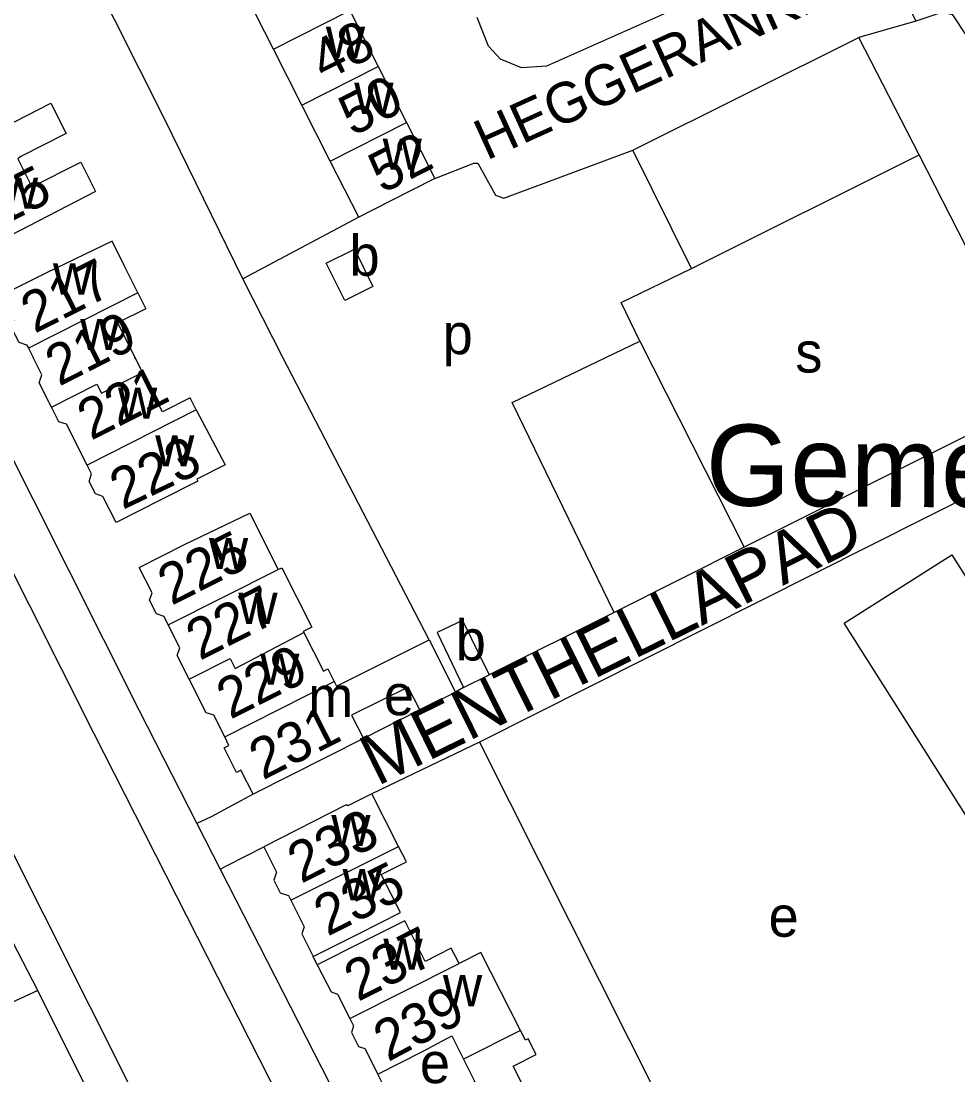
# Model space of a CAD drawing. Extents: x 161258 to 163262, y 380749 to 382054.
# Drawn here: x 162448.7 to 162541.1, y 381429.2 to 381533.2 of the extents above; entities that cross this region are included whole.
import ezdxf

# ---------------------------------------------------------------- set-up
doc = ezdxf.new("R2010")
doc.units = 0
for name, color, linetype in [('BLT_Basislijn', 7, 'Continuous'), ('BLT_Bebouwing', 7, 'Continuous'), ('BLT_Bebouwing_beschrifting', 7, 'Continuous'), ('BLT_Centroide', 7, 'Continuous'), ('BLT_Huisnummer', 7, 'Continuous'), ('BLT_Huisnummer_ tussenligend', 7, 'Continuous'), ('BLT_Onderverdeling_panden', 7, 'Continuous'), ('BLT_Straatnaam', 7, 'Continuous'), ('BLT_Straatnaam_verkleind', 7, 'Continuous')]:
    doc.layers.add(name, color=color, linetype=linetype)

msp = doc.modelspace()

# ---------------------------------------------------------------- linework, layer by layer
at = {"layer": 'BLT_Basislijn'}
for p, q in [((162416.03, 381553.18), (162460.34, 381465.23)), ((162411.57, 381550.93), (162455.87, 381462.98)), ((162536.9, 381533.15), (162531.28, 381531.53)), ((162537.23, 381519.98), (162531.28, 381531.53)), ((162514.8, 381508.76), (162509, 381520.42)), ((162514.8, 381508.76), (162537.23, 381519.98)), ((162547.55, 381499.74), (162537.23, 381519.98)), ((162482, 381513.83), (162470.57, 381507.75)), ((162507.86, 381505.42), (162514.8, 381508.76)), ((162509.71, 381501.59), (162507.86, 381505.42)), ((162497.11, 381495.54), (162509.71, 381501.59)), ((162509.71, 381501.59), (162520, 381481.27)), ((162560.67, 381495.67), (162493.89, 381462.07)), ((162549.4, 381496.02), (162520, 381481.27)), ((162507.17, 381474.84), (162497.11, 381495.54)), ((162520, 381481.27), (162507.17, 381474.84)), ((162435.76, 381475.3), (162471.25, 381404.61)), ((162507.17, 381474.84), (162494.86, 381468.68)), ((162492.34, 381467.44), (162491.54, 381466.98)), ((162460.34, 381465.23), (162466.05, 381454.03)), ((162488.02, 381465.23), (162482.46, 381462.42)), ((162455.87, 381462.98), (162475.39, 381424.52)), ((162493.89, 381462.07), (162483.3, 381456.97)), ((162493.89, 381462.07), (162518.15, 381413.86)), ((162471.59, 381456.91), (162467.46, 381454.7)), ((162467.46, 381454.7), (162466.05, 381454.03)), ((162466.05, 381454.03), (162468.35, 381449.53)), ((162469.05, 381449.89), (162472.64, 381451.74)), ((162468.35, 381449.53), (162469.05, 381449.89)), ((162468.35, 381449.53), (162480.15, 381426.41)), ((162477.92, 381440.11), (162477.51, 381440.92)), ((162450.39, 381437.58), (162444.45, 381434.82)), ((162460.82, 381416.55), (162450.39, 381437.58)), ((162486.13, 381424.89), (162483.88, 381429.32))]:
    msp.add_line(p, q, dxfattribs=at)
for points in [[(162450.39, 381437.58), (162418.09, 381500), (162384.62, 381565.32)], [(162470.57, 381507.75), (162462.89, 381523.46), (162443.04, 381562.88)], [(162532.07, 381550.22), (162534.53, 381545.25), (162534.67, 381544.33), (162533.91, 381543.61), (162500.52, 381528.7), (162498.03, 381528.54), (162495.96, 381529.41), (162494.78, 381530.68), (162493.68, 381533.5)], [(162631.05, 381395.39), (162633.35, 381398.89), (162632.9, 381403.53), (162624.97, 381412.12), (162615.66, 381424.45), (162600, 381449.93), (162569.46, 381500), (162544.3, 381537.15), (162543.02, 381538.49), (162542.38, 381538.78), (162539.8, 381539.21), (162535.12, 381537.37), (162535.12, 381536.9), (162536.9, 381533.15)], [(162549.4, 381496.02), (162556.96, 381500), (162560.62, 381501.86), (162560.84, 381502.53), (162549.84, 381519.11), (162545.67, 381526.01), (162540.54, 381533.77), (162539.48, 381534.01), (162536.9, 381533.15)], [(162509, 381520.42), (162531.28, 381531.53)], [(162489.51, 381517.63), (162493.36, 381519.16), (162493.74, 381519.16), (162495.47, 381515.98), (162496.29, 381515.7), (162509, 381520.42)], [(162488.94, 381472.14), (162474.51, 381500), (162470.57, 381507.75)]]:
    msp.add_lwpolyline(points, dxfattribs=at)
at = {"layer": 'BLT_Bebouwing'}
for p, q in [((162473.61, 381530.38), (162470.82, 381535.9)), ((162481.13, 381534.19), (162483.92, 381528.67)), ((162476.41, 381524.87), (162473.61, 381530.38)), ((162483.92, 381528.67), (162486.71, 381523.15)), ((162479.2, 381519.35), (162476.41, 381524.87)), ((162486.71, 381523.15), (162489.51, 381517.63)), ((162482, 381513.83), (162479.2, 381519.35)), ((162449.44, 381500.91), (162449.9, 381500)), ((162460, 381499.88), (162459.94, 381500)), ((162492.24, 381474.06), (162494.86, 381468.68)), ((162492.34, 381467.44), (162494.86, 381468.68)), ((162488.02, 381465.23), (162491.54, 381466.98)), ((162482.46, 381462.42), (162471.59, 381456.91)), ((162552.63, 381437.72), (162537.06, 381462.39)), ((162485.93, 381451.77), (162483.3, 381456.97))]:
    msp.add_line(p, q, dxfattribs=at)
for points in [[(162445.35, 381525.55), (162446.85, 381522.6), (162451.66, 381525.05), (162453.17, 381522.08), (162448.7, 381519.81), (162448.39, 381519.59)], [(162448.39, 381519.59), (162449.8, 381516.82), (162454.6, 381519.26), (162456.07, 381516.37), (162447.61, 381511.99), (162443.15, 381509.72), (162441.61, 381512.75), (162440.95, 381512.97), (162440.25, 381514.34), (162440.48, 381515.05), (162440.27, 381515.45)], [(162489.51, 381517.63), (162485.05, 381515.37), (162482, 381513.83)], [(162460.23, 381506.37), (162458.9, 381509.07), (162457.71, 381511.45), (162451.22, 381508.35), (162446.76, 381506.09), (162447.99, 381503.64), (162447.76, 381502.93), (162448.49, 381501.49), (162449.27, 381501.24), (162449.44, 381500.91)], [(162460.23, 381506.37), (162461.02, 381504.8), (162458.22, 381503.39), (162460.68, 381498.52)], [(162451.71, 381495.1), (162450.5, 381497.49), (162450.76, 381498.29), (162449.9, 381500)], [(162465.99, 381494.82), (162465.39, 381496.01), (162462.66, 381494.63), (162460.68, 381498.52)], [(162455.24, 381489.38), (162453.21, 381493.4), (162452.44, 381493.65), (162451.71, 381495.1)], [(162465.99, 381494.82), (162468.85, 381489.4), (162466.04, 381487.98), (162466.14, 381487.78), (162462.55, 381485.97), (162458.09, 381483.71)], [(162458.09, 381483.71), (162456.79, 381486.28), (162456.05, 381486.53), (162455.43, 381487.75), (162455.68, 381488.52), (162455.24, 381489.38)], [(162460.35, 381479.29), (162464.82, 381481.55), (162471.26, 381484.63), (162474.07, 381479.08)], [(162537.06, 381462.39), (162529.85, 381473.8), (162540.47, 381480.51), (162552.78, 381461)], [(162463.23, 381473.64), (162462.81, 381474.46), (162462.06, 381474.71), (162461.39, 381476.04), (162461.63, 381476.77), (162460.35, 381479.29)], [(162474.07, 381479.08), (162474.42, 381479.26), (162477.39, 381473.39)], [(162492.24, 381474.06), (162489.74, 381472.86), (162492.34, 381467.44)], [(162465.29, 381468.27), (162464.12, 381470.59), (162464.38, 381471.37), (162463.23, 381473.64)], [(162477.39, 381473.39), (162476.54, 381472.96), (162476.59, 381472.86)], [(162476.59, 381472.86), (162478.52, 381469.06), (162478.95, 381469.28), (162479.59, 381468.02)], [(162479.59, 381468.02), (162479.82, 381467.56), (162488.94, 381472.14)], [(162488.94, 381472.14), (162491.54, 381466.98)], [(162468.79, 381462.59), (162467.71, 381464.71), (162466.97, 381464.95), (162465.29, 381468.27)], [(162488.02, 381465.23), (162486.89, 381467.48), (162481.29, 381464.73), (162482.46, 381462.42)], [(162471.59, 381456.91), (162470.39, 381459.28), (162469.96, 381459.07), (162468.73, 381461.5), (162469.21, 381461.74), (162468.79, 381462.59)], [(162483.3, 381456.97), (162480.92, 381455.76), (162480.77, 381455.86), (162472.64, 381451.74)], [(162472.64, 381451.74), (162473.9, 381449.25), (162473.64, 381448.44), (162474.27, 381447.2), (162475.07, 381446.93), (162475.31, 381446.47)], [(162477.51, 381440.92), (162481.97, 381443.17), (162486.12, 381445.26), (162484.22, 381449), (162486.7, 381450.26), (162485.93, 381451.77)], [(162475.31, 381446.47), (162476.62, 381443.86), (162476.39, 381443.14), (162477.51, 381440.92)], [(162491.89, 381440.22), (162491.12, 381441.73), (162488.56, 381440.43), (162486.54, 381444.44), (162482.39, 381442.35), (162477.92, 381440.11)], [(162497.96, 381433.61), (162494.02, 381441.31), (162491.89, 381440.22)], [(162477.92, 381440.11), (162479.28, 381437.43), (162479.9, 381437.22), (162481.12, 381434.82)], [(162481.12, 381434.82), (162481.49, 381434.08), (162481.28, 381433.43), (162481.98, 381432.05), (162482.6, 381431.84), (162483.88, 381429.32)], [(162496.96, 381423.89), (162495.65, 381426.46), (162498.36, 381427.83), (162497.21, 381430.1), (162499.48, 381431.27), (162498.69, 381432.81), (162498.44, 381432.68), (162497.96, 381433.61)], [(162483.88, 381429.32), (162488.34, 381431.58), (162491.17, 381433.08), (162492.32, 381430.8)], [(162492.32, 381430.8), (162493.46, 381428.55), (162486.13, 381424.89)]]:
    msp.add_lwpolyline(points, dxfattribs=at)
msp.add_lwpolyline([(162478.8, 381509.3), (162481.57, 381510.67), (162483.39, 381507), (162480.62, 381505.62)], close=True, dxfattribs=at)
at = {"layer": 'BLT_Onderverdeling_panden'}
for p, q in [((162473.61, 381530.38), (162481.13, 381534.19)), ((162476.41, 381524.87), (162483.92, 381528.67)), ((162479.2, 381519.35), (162486.71, 381523.15)), ((162460.23, 381506.37), (162449.44, 381500.91)), ((162465.99, 381494.82), (162455.24, 381489.38)), ((162463.23, 381473.64), (162474.07, 381479.08)), ((162468.79, 381462.59), (162479.59, 381468.02)), ((162475.31, 381446.47), (162485.93, 381451.77)), ((162481.12, 381434.82), (162491.89, 381440.22)), ((162497.96, 381433.61), (162492.32, 381430.8))]:
    msp.add_line(p, q, dxfattribs=at)
for points in [[(162451.71, 381495.1), (162456.2, 381497.37), (162456.65, 381496.48), (162460.68, 381498.52)], [(162465.29, 381468.27), (162469.34, 381470.3), (162469.83, 381469.32), (162476.59, 381472.86)]]:
    msp.add_lwpolyline(points, dxfattribs=at)

# ---------------------------------------------------------------- texts
at = {"layer": 'BLT_Bebouwing_beschrifting'}
msp.add_text('Gemeenschapshuis', height=7.9999, rotation=359.548, dxfattribs=at).set_placement((162516.18, 381485.4))
at = {"layer": 'BLT_Centroide'}
for s, p in [('w', (162478.77, 381529.53)), ('w', (162481.56, 381524)), ('w', (162484.36, 381518.5)), ('w', (162446.55, 381514.66)), ('b', (162481.09, 381508.04)), ('w', (162451.87, 381506.19)), ('w', (162454.55, 381500.72)), ('p', (162490.27, 381500.31)), ('s', (162525.03, 381498.5)), ('w', (162458.28, 381493.94)), ('w', (162461.94, 381489.25)), ('w', (162467.24, 381479.12)), ('w', (162470.14, 381473.72)), ('b', (162491.56, 381470.11)), ('w', (162472.29, 381467.72)), ('m', (162477.02, 381464.53)), ('e', (162484.48, 381464.71)), ('w', (162479.3, 381451.81)), ('w', (162480.41, 381446.47)), ('e', (162522.39, 381442.87)), ('w', (162484.43, 381439.62)), ('w', (162490.3, 381436.02)), ('e', (162488.03, 381428.43))]:
    msp.add_text(s, height=4, dxfattribs=at).set_placement(p)
at = {"layer": 'BLT_Huisnummer'}
for s, rotation, p in [('52', 26.8367, (162484.32, 381516.11)), ('215', 26.9698, (162444.06, 381511.49)), ('217', 26.8466, (162450.06, 381502.31)), ('223', 25.5496, (162458.74, 381484.94)), ('225', 26.859, (162463.55, 381475.48)), ('231', 26.8547, (162472.55, 381458.27)), ('233', 26.7547, (162476.33, 381448.07)), ('239', 27.9921, (162484.88, 381430.49))]:
    msp.add_text(s, height=4, rotation=rotation, dxfattribs=at).set_placement(p)
at = {"layer": 'BLT_Huisnummer_ tussenligend'}
for s, rotation, p in [('48', 26.8544, (162478.59, 381527.17)), ('50', 26.8544, (162481.39, 381521.75)), ('219', 26.8466, (162452.47, 381497.1)), ('221', 26.8466, (162455.62, 381491.76)), ('227', 26.859, (162466.34, 381470.06)), ('229', 26.859, (162469.35, 381464.25)), ('235', 26.7547, (162478.93, 381442.86)), ('237', 26.7547, (162481.93, 381436.43))]:
    msp.add_text(s, height=4, rotation=rotation, dxfattribs=at).set_placement(p)
at = {"layer": 'BLT_Straatnaam'}
msp.add_text('MENTHELLAPAD', height=5, rotation=26.3258, dxfattribs=at).set_placement((162483.82, 381457.68))
at = {"layer": 'BLT_Straatnaam_verkleind'}
msp.add_text('HEGGERANKLAAN', height=4, rotation=24.5029, dxfattribs=at).set_placement((162494.6, 381519.38))

doc.saveas('drawing.dxf')
